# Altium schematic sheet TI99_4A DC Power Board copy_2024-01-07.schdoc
size 264 x 144 mm
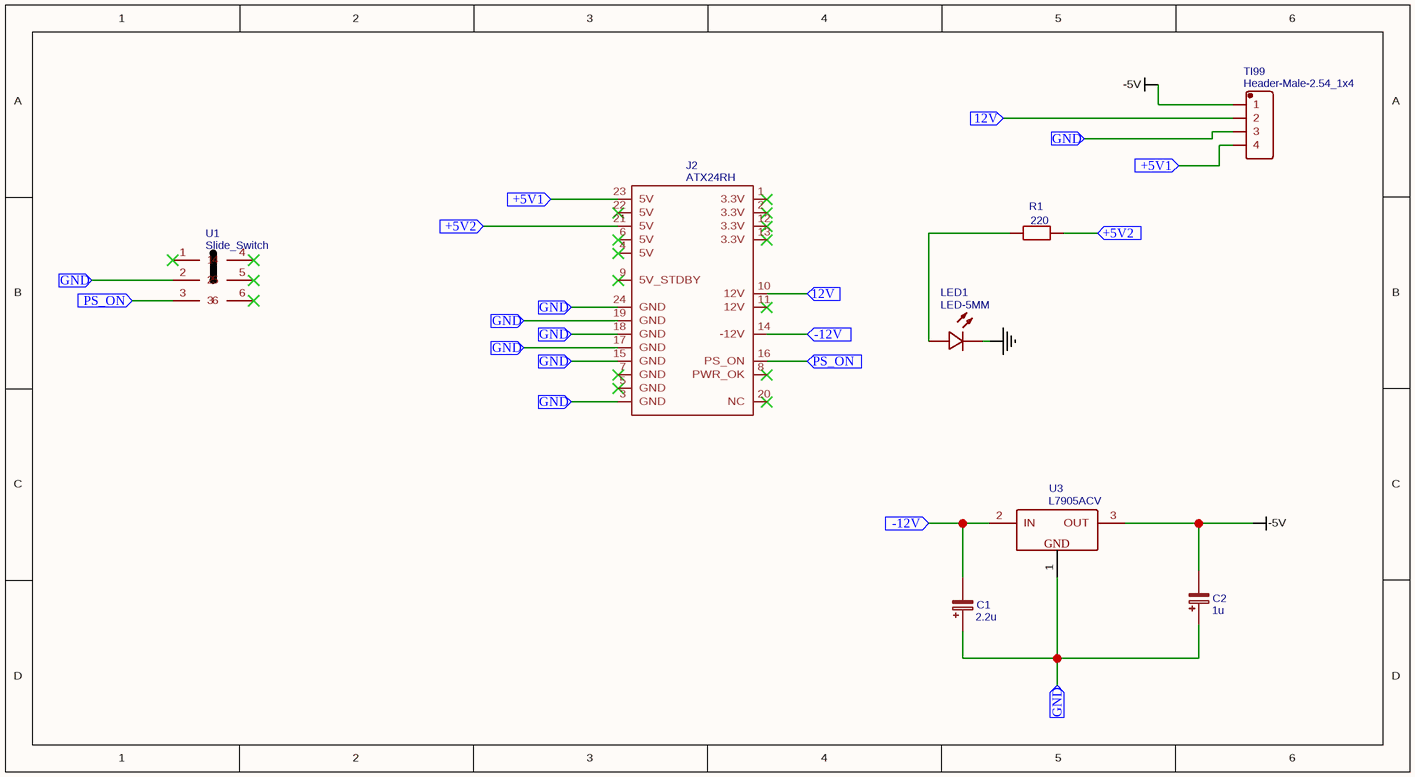
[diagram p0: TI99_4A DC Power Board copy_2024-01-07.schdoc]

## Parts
C1  2.2u  [CASE-C_6032]
C2  1u  [CASE-C_6032]
J2  ATX24RH  [ATX24_RIGHT_ANGLE]
LED1  LED-5MM  [LED-5MM/2.54]
R1  220  [L_AXIAL-0.4]
TI99  Header-Male-2.54_1x4  [DIP-1X4P-3.96MM-SK]
U1  Slide_Switch  [SLIDE_SWITCH]
U3  L7905ACV  [TO220]

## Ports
12V (in), +5V1 (in), +5V2 (in), -12V (in), GND (in), PS_ON (in)

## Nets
-5V: C2.2 TI99.1 U3.3(OUT)
GND: LED1.2(-)
12V: J2.10(12V) TI99.2 ; port 12V
+5V1: J2.23(5V) TI99.4 ; port +5V1
+5V2: J2.21(5V) R1.1 ; port +5V2
-12V: C1.2 J2.14(-12V) U3.2(IN) ; port -12V
GND: C1.1 C2.1 J2.3(GND) J2.15(GND) J2.17(GND) J2.18(GND) J2.19(GND) J2.24(GND) TI99.3 U1.2 U3.1(GND) ; port GND  [a separate net that carries the same name]
PS_ON: J2.16(PS_ON) U1.3 ; port PS_ON
NetLED1_1: LED1.1(+) R1.2

Not connected (* = marked no-connect by the designer): J2 1(3.3V)* 2(3.3V)* 4(5V)* 5(GND)* 6(5V)* 7(GND)* 8(PWR_OK)* 9(5V_STDBY)* 11(12V)* 12(3.3V)* 13(3.3V)* 20(NC)* 22(5V)*; U1 1* 4* 5* 6*

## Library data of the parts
C1 = 2.2u: nameAlias: Value(F); Contributor: LCEDA_Lib
C2 = 1u: nameAlias: Value(F); Contributor: LCEDA_Lib
J2 = ATX24RH: description: ATX24 Pin Power Supply Connector This is a good connector for connecting a computer power supply to a PCB. Its massive, but provides many amps of power at 5V and 12V. SKU: PRT-09498; Contributor: SparkFun
LED1 = LED-5MM: Manufacturer: EVERLIGHT; Manufacturer Part: 5AR2ST10
R1 = 220: nameAlias: Value(Ω)
TI99 = Header-Male-2.54_1x4: Manufacturer: Ckmtw; Manufacturer Part: 210S-1*4P L=11.6MMGold-plated black; Contributor: LCSC
U1 = Slide_Switch: nameAlias: Model; Contributor: mosk22rte
U3 = L7905ACV: description: 2% Negative Voltage Regulator, -5V, 3-Pin TO-220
